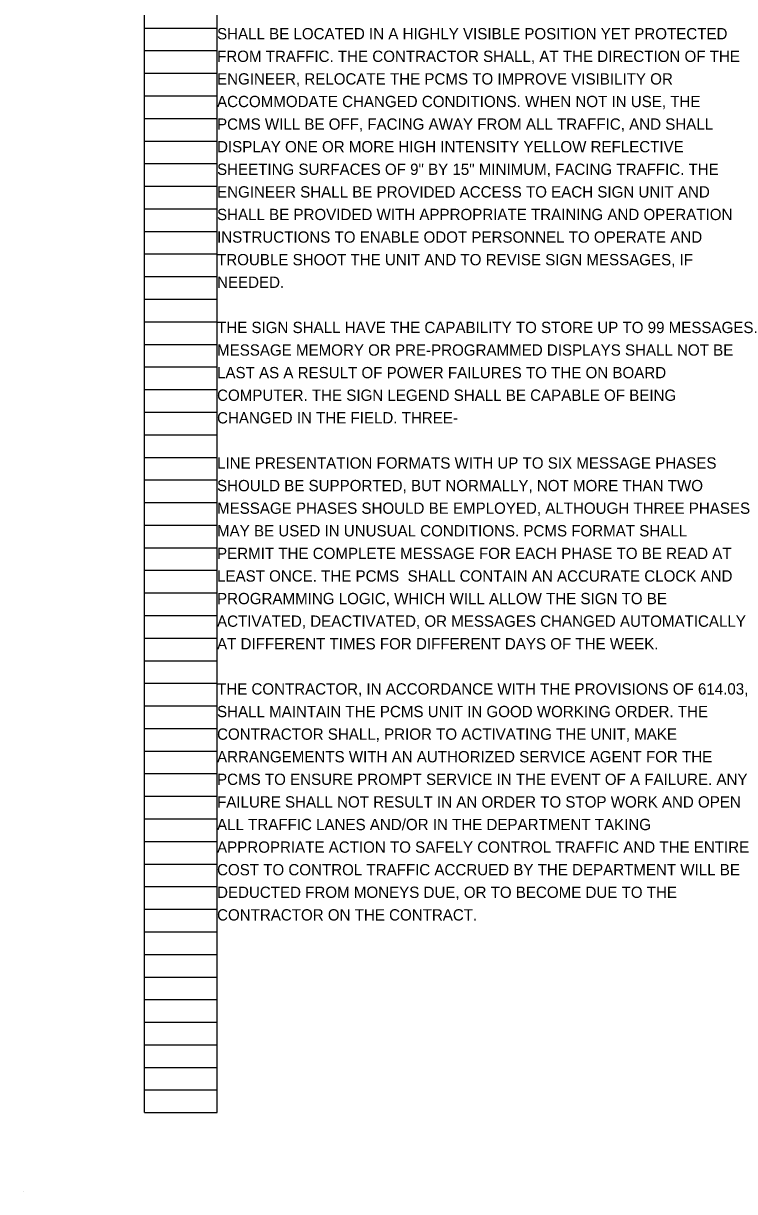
# Model space of a CAD drawing. Extents: x 24172 to 24226.9, y 11011.9 to 11091.2.
# Drawn here: x 24194.95 to 24203.76, y 11011.89 to 11026.37 of the extents above; entities that cross this region are included whole.
import ezdxf

# ---------------------------------------------------------------- set-up
doc = ezdxf.new("R2010")
doc.units = 0
doc.layers.add('SC_Scratch1', color=7, linetype='Continuous')
doc.layers.add('SH_Data', color=7, linetype='Continuous')

msp = doc.modelspace()

# ---------------------------------------------------------------- linework, layer by layer
at = {"layer": 'SH_Data'}
for p, q in [((24196.45, 11012.874), (24196.45, 11033.034)), ((24197.35, 11012.874), (24197.35, 11033.034)), ((24196.45, 11026.314), (24197.35, 11026.314)), ((24196.45, 11026.034), (24197.35, 11026.034)), ((24196.45, 11025.754), (24197.35, 11025.754)), ((24196.45, 11025.474), (24197.35, 11025.474)), ((24196.45, 11025.194), (24197.35, 11025.194)), ((24196.45, 11024.914), (24197.35, 11024.914)), ((24196.45, 11024.634), (24197.35, 11024.634)), ((24196.45, 11024.354), (24197.35, 11024.354)), ((24196.45, 11024.074), (24197.35, 11024.074)), ((24196.45, 11023.794), (24197.35, 11023.794)), ((24196.45, 11023.514), (24197.35, 11023.514)), ((24196.45, 11023.234), (24197.35, 11023.234)), ((24196.45, 11022.954), (24197.35, 11022.954)), ((24196.45, 11022.674), (24197.35, 11022.674)), ((24196.45, 11022.394), (24197.35, 11022.394)), ((24196.45, 11022.114), (24197.35, 11022.114)), ((24196.45, 11021.834), (24197.35, 11021.834)), ((24196.45, 11021.554), (24197.35, 11021.554)), ((24196.45, 11021.274), (24197.35, 11021.274)), ((24196.45, 11020.994), (24197.35, 11020.994)), ((24196.45, 11020.714), (24197.35, 11020.714)), ((24196.45, 11020.434), (24197.35, 11020.434)), ((24196.45, 11020.154), (24197.35, 11020.154)), ((24196.45, 11019.874), (24197.35, 11019.874)), ((24196.45, 11019.594), (24197.35, 11019.594)), ((24196.45, 11019.314), (24197.35, 11019.314)), ((24196.45, 11019.034), (24197.35, 11019.034)), ((24196.45, 11018.754), (24197.35, 11018.754)), ((24196.45, 11018.474), (24197.35, 11018.474)), ((24196.45, 11018.194), (24197.35, 11018.194)), ((24196.45, 11017.914), (24197.35, 11017.914)), ((24196.45, 11017.634), (24197.35, 11017.634)), ((24196.45, 11017.354), (24197.35, 11017.354)), ((24196.45, 11017.074), (24197.35, 11017.074)), ((24196.45, 11016.794), (24197.35, 11016.794)), ((24196.45, 11016.514), (24197.35, 11016.514)), ((24196.45, 11016.234), (24197.35, 11016.234)), ((24196.45, 11015.954), (24197.35, 11015.954)), ((24196.45, 11015.674), (24197.35, 11015.674)), ((24196.45, 11015.394), (24197.35, 11015.394)), ((24196.45, 11015.114), (24197.35, 11015.114)), ((24196.45, 11014.834), (24197.35, 11014.834)), ((24196.45, 11014.554), (24197.35, 11014.554)), ((24196.45, 11014.274), (24197.35, 11014.274)), ((24196.45, 11013.994), (24197.35, 11013.994)), ((24196.45, 11013.714), (24197.35, 11013.714)), ((24196.45, 11013.434), (24197.35, 11013.434)), ((24196.45, 11013.154), (24197.35, 11013.154)), ((24196.45, 11012.874), (24197.35, 11012.874)), ((24194.95, 11011.894), (24194.95, 11011.894))]:
    msp.add_line(p, q, dxfattribs=at)

# ---------------------------------------------------------------- texts
at = {"layer": 'SC_Scratch1'}
for s, p in [('SHALL BE LOCATED IN A HIGHLY VISIBLE POSITION YET PROTECTED ', (24197.35, 11026.174)), ('FROM TRAFFIC. THE CONTRACTOR SHALL, AT THE DIRECTION OF THE ', (24197.35, 11025.894)), ('ENGINEER, RELOCATE THE PCMS TO IMPROVE VISIBILITY OR ', (24197.35, 11025.614)), ('ACCOMMODATE CHANGED CONDITIONS. WHEN NOT IN USE, THE ', (24197.35, 11025.334)), ('PCMS WILL BE OFF, FACING AWAY FROM ALL TRAFFIC, AND SHALL ', (24197.35, 11025.054)), ('DISPLAY ONE OR MORE HIGH INTENSITY YELLOW REFLECTIVE ', (24197.35, 11024.774)), ('SHEETING SURFACES OF 9" BY 15" MINIMUM, FACING TRAFFIC. THE ', (24197.35, 11024.494)), ('ENGINEER SHALL BE PROVIDED ACCESS TO EACH SIGN UNIT AND ', (24197.35, 11024.214)), ('SHALL BE PROVIDED WITH APPROPRIATE TRAINING AND OPERATION ', (24197.35, 11023.934)), ('INSTRUCTIONS TO ENABLE ODOT PERSONNEL TO OPERATE AND ', (24197.35, 11023.654)), ('TROUBLE SHOOT THE UNIT AND TO REVISE SIGN MESSAGES, IF ', (24197.35, 11023.374)), ('NEEDED.', (24197.35, 11023.094)), ('THE SIGN SHALL HAVE THE CAPABILITY TO STORE UP TO 99 MESSAGES. ', (24197.35, 11022.534)), ('MESSAGE MEMORY OR PRE-PROGRAMMED DISPLAYS SHALL NOT BE ', (24197.35, 11022.254)), ('LAST AS A RESULT OF POWER FAILURES TO THE ON BOARD ', (24197.35, 11021.974)), ('COMPUTER. THE SIGN LEGEND SHALL BE CAPABLE OF BEING ', (24197.35, 11021.694)), ('CHANGED IN THE FIELD. THREE-', (24197.35, 11021.414)), ('LINE PRESENTATION FORMATS WITH UP TO SIX MESSAGE PHASES ', (24197.35, 11020.854)), ('SHOULD BE SUPPORTED, BUT NORMALLY, NOT MORE THAN TWO ', (24197.35, 11020.574)), ('MESSAGE PHASES SHOULD BE EMPLOYED, ALTHOUGH THREE PHASES ', (24197.35, 11020.294)), ('MAY BE USED IN UNUSUAL CONDITIONS. PCMS FORMAT SHALL ', (24197.35, 11020.014)), ('PERMIT THE COMPLETE MESSAGE FOR EACH PHASE TO BE READ AT ', (24197.35, 11019.734)), ('LEAST ONCE. THE PCMS  SHALL CONTAIN AN ACCURATE CLOCK AND ', (24197.35, 11019.454)), ('PROGRAMMING LOGIC, WHICH WILL ALLOW THE SIGN TO BE ', (24197.35, 11019.174)), ('ACTIVATED, DEACTIVATED, OR MESSAGES CHANGED AUTOMATICALLY ', (24197.35, 11018.894)), ('AT DIFFERENT TIMES FOR DIFFERENT DAYS OF THE WEEK.', (24197.35, 11018.614)), ('THE CONTRACTOR, IN ACCORDANCE WITH THE PROVISIONS OF 614.03, ', (24197.35, 11018.054)), ('SHALL MAINTAIN THE PCMS UNIT IN GOOD WORKING ORDER. THE ', (24197.35, 11017.774)), ('CONTRACTOR SHALL, PRIOR TO ACTIVATING THE UNIT, MAKE ', (24197.35, 11017.494)), ('ARRANGEMENTS WITH AN AUTHORIZED SERVICE AGENT FOR THE ', (24197.35, 11017.214)), ('PCMS TO ENSURE PROMPT SERVICE IN THE EVENT OF A FAILURE. ANY ', (24197.35, 11016.934)), ('FAILURE SHALL NOT RESULT IN AN ORDER TO STOP WORK AND OPEN ', (24197.35, 11016.654)), ('ALL TRAFFIC LANES AND/OR IN THE DEPARTMENT TAKING ', (24197.35, 11016.374)), ('APPROPRIATE ACTION TO SAFELY CONTROL TRAFFIC AND THE ENTIRE ', (24197.35, 11016.094)), ('COST TO CONTROL TRAFFIC ACCRUED BY THE DEPARTMENT WILL BE ', (24197.35, 11015.814)), ('DEDUCTED FROM MONEYS DUE, OR TO BECOME DUE TO THE ', (24197.35, 11015.534)), ('CONTRACTOR ON THE CONTRACT.', (24197.35, 11015.254))]:
    msp.add_text(s, height=0.14, dxfattribs=at).set_placement(p)

doc.saveas('drawing.dxf')
